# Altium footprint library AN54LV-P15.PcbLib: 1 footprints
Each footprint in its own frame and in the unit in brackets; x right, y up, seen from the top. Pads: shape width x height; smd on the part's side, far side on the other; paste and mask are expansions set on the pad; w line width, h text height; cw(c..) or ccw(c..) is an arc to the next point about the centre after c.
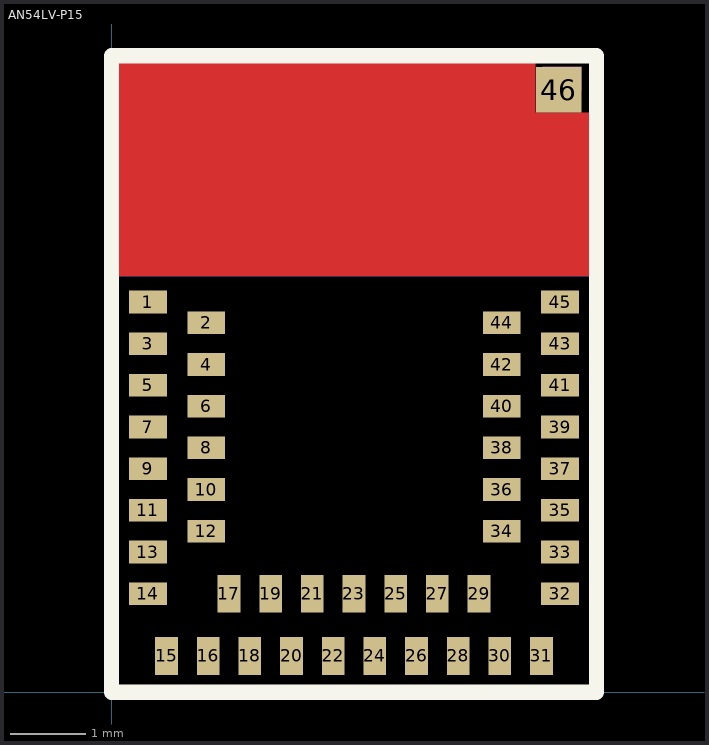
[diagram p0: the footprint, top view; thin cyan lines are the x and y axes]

## AN54LV-P15 [mm]
pads (46):
  rect 0.5x0.3 smd mask+0: 1(0.48,5.15) 2(1.25,4.875) 3(0.48,4.6) 4(1.25,4.325) 5(0.48,4.05) 6(1.25,3.775) 7(0.48,3.5) 8(1.25,3.225) 9(0.48,2.95) 10(1.25,2.675) 11(0.48,2.4) 12(1.25,2.125) 13(0.48,1.85) 14(0.48,1.3) 32(5.92,1.3) 33(5.92,1.85) 34(5.15,2.125) 35(5.92,2.4) 36(5.15,2.675) 37(5.92,2.95) 38(5.15,3.225) 39(5.92,3.5) 40(5.15,3.775) 41(5.92,4.05) 42(5.15,4.325) 43(5.92,4.6) 44(5.15,4.875) 45(5.92,5.15)
  rect 0.3x0.5 smd mask+0: 15(0.725,0.48) 16(1.275,0.48) 17(1.55,1.3) 18(1.825,0.48) 19(2.1,1.3) 20(2.375,0.48) 21(2.65,1.3) 22(2.925,0.48) 23(3.2,1.3) 24(3.475,0.48) 25(3.75,1.3) 26(4.025,0.48) 27(4.3,1.3) 28(4.575,0.48) 29(4.85,1.3) 30(5.125,0.48) 31(5.675,0.48)
  rect 0.6x0.6 smd mask+0: 46(5.9,7.95)
Top Layer:
  pour cut-out: 0,8.4 0,5.5 6.4,5.5 6.4,7.646 5.595,7.646 5.595,8.4
Top Overlay:
  lines w0.2: 0,0 0,8.4 6.4,8.4 6.4,0 0,0
Mechanical 2:
  lines w0.01: 0,5.5 6.4,5.5 ; 5.7,7.955 6.2,7.955 6.2,8.255 5.7,8.255 5.7,7.955
  text "No Ground Pad" at 0.92,6.38 h0.45
Mechanical 9:
  lines w0.01: 0,5.4 0,8.4 ; 6.4,5.4 6.4,8.4 ; 0,8.4 6.4,8.4 ; 0,8.4 0,0 6.4,0 6.4,8.4 ; 0,8.4 6.4,8.4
